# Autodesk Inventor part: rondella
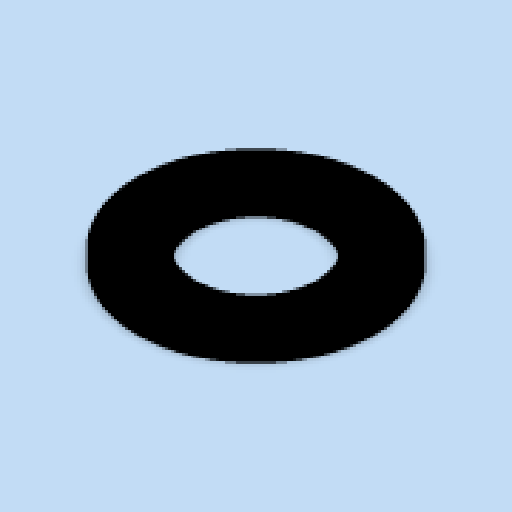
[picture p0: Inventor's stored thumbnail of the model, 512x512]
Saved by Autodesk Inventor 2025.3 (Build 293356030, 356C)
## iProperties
Created: 2026-05
Part Number: rondella
Material: Generico
Document SubType Name: Modeling
Designer: R5800u
Density: 1 g/cm^3
Appearance: Anodizzato - Nero
Author: R5800u
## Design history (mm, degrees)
sketch "Schizzo1"
  geometry: C1 r 1.75 at (0, 0); C2 r 3.5 at (0, 0); 1 further point
  constraints: 2 centre point, 2 coincident
  dimensions: "d0" = 3.5 diameter of C1; "d1" = 7 diameter of C2
extrude "Estrusione1" new body sketch "Schizzo1" distance "d2" = 0.5; taper "d3" = 0 deg
node "Solido1"
